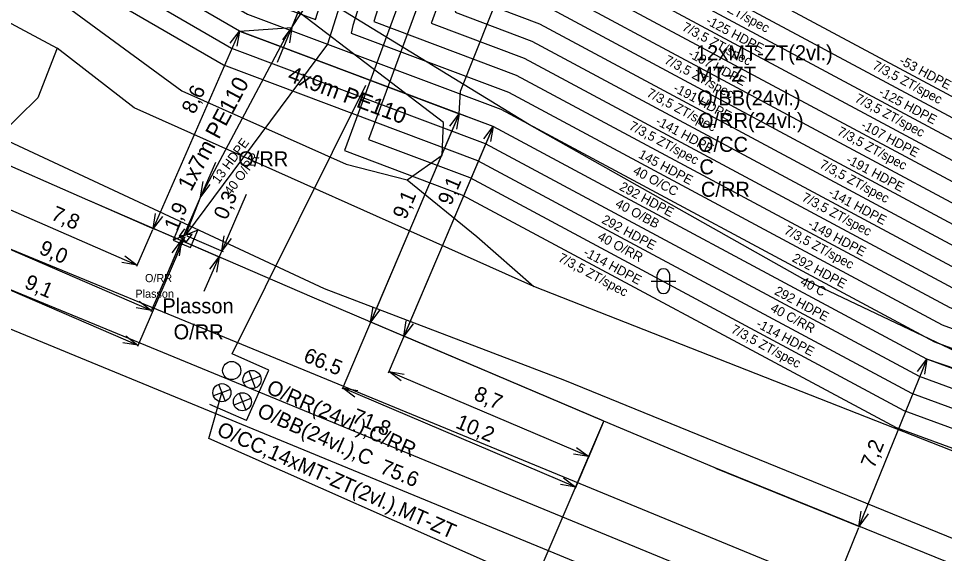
# Model space of a CAD drawing. Extents: x -836739 to -834468, y -1071001 to -1070126.
# Drawn here: x -836416.85 to -836379.75, y -1070403.2 to -1070381.77 of the extents above; entities that cross this region are included whole.
import ezdxf

# ---------------------------------------------------------------- set-up
doc = ezdxf.new("R2010")
doc.units = 0
for name, color, linetype in [('f001_pol_linie', 7, 'Continuous'), ('f001_pol_znacky', 7, 'Continuous'), ('f003_opt_sit_texty', 7, 'Continuous'), ('f003_opt_sit_znacky', 7, 'Continuous'), ('f006_osa_trasy', 7, 'Continuous'), ('f006_stp_koty', 7, 'Continuous'), ('f006_stp_linie', 7, 'Continuous'), ('f006_stp_texty', 7, 'Continuous'), ('f007_rezkynet_linie', 7, 'Continuous'), ('f007_rezkynet_texty', 7, 'Continuous'), ('f007_rezkynet_znacky', 7, 'Continuous'), ('f309_trub_konc_zar', 7, 'Continuous'), ('f309_trub_konc_zar_ann', 7, 'Continuous'), ('f309_trubicka', 7, 'Continuous'), ('f309_trubicka_ann', 7, 'Continuous'), ('f309_trubka', 7, 'Continuous'), ('f309_trubka_ann', 7, 'Continuous')]:
    doc.layers.add(name, color=color, linetype=linetype)

msp = doc.modelspace()

# ---------------------------------------------------------------- linework, layer by layer
at = {"layer": 'f001_pol_linie'}
for points in [[(-836356.62, -1070406.87), (-836370.19, -1070399.44), (-836385.43, -1070392.2), (-836396.38, -1070386.03), (-836404.41, -1070381.11), (-836409.87, -1070376.61), (-836425.28, -1070363.93), (-836449.03, -1070345.44), (-836455, -1070340), (-836462.64, -1070329.11), (-836464.81, -1070325.47), (-836465.74, -1070321.03), (-836464.89, -1070314.87), (-836461.62, -1070306.74), (-836456.41, -1070297.54), (-836450.95, -1070288.2), (-836447.03, -1070272.79), (-836441.38, -1070260.76)], [(-836496.52, -1070319.54), (-836488.05, -1070326.94), (-836479.74, -1070333.71), (-836473.51, -1070339.57), (-836464.27, -1070347.56), (-836456.25, -1070354.2), (-836445.54, -1070362.45), (-836432.86, -1070371.82), (-836421.65, -1070379.55), (-836415.3, -1070382.95)], [(-836490.91, -1070321.78), (-836479.74, -1070331.15), (-836472.55, -1070338.03), (-836463.6, -1070345.51), (-836457.27, -1070350.28), (-836449.01, -1070356.39), (-836440.87, -1070363.54), (-836429.17, -1070372.36), (-836419.16, -1070378.17), (-836410.31, -1070384.67), (-836403.72, -1070387.61), (-836401.28, -1070388.23), (-836398.49, -1070390.5), (-836396.2, -1070392.51)], [(-836401.28, -1070388.23), (-836399.88, -1070387.24), (-836399.82, -1070385.94), (-836405.57, -1070381.55), (-836407.8, -1070379.27), (-836409.87, -1070376.61)], [(-836415.3, -1070382.95), (-836416.08, -1070384.95), (-836417.67, -1070386.5), (-836418.22, -1070387.23)], [(-836363.94, -1070405.58), (-836375.83, -1070400.5), (-836396.2, -1070392.51), (-836412.22, -1070385.35), (-836415.3, -1070382.95)], [(-836417.67, -1070386.5), (-836404.61, -1070392.58), (-836394.98, -1070396.26), (-836377.21, -1070403.49), (-836366.86, -1070407.51), (-836361.89, -1070409.63)], [(-836393.4, -1070397.9), (-836405, -1070392.97), (-836414.08, -1070389.04), (-836418.22, -1070387.23), (-836418.59, -1070387.07)], [(-836407.72, -1070434.26), (-836404.42, -1070424.71), (-836401.63, -1070417.07), (-836396.94, -1070406.16), (-836393.4, -1070397.9)], [(-836369.71, -1070407.51), (-836374.95, -1070405.45), (-836388.98, -1070399.76), (-836393.4, -1070397.9)]]:
    msp.add_lwpolyline(points, dxfattribs=at)
at = {"layer": 'f001_pol_znacky'}
for p, q in [((-836391.26, -1070392.54), (-836391.26, -1070392.04)), ((-836390.76, -1070392.54), (-836390.76, -1070392.04)), ((-836391.51, -1070392.29), (-836390.51, -1070392.29))]:
    msp.add_line(p, q, dxfattribs=at)
for centre, start, end in [((-836391.01, -1070392.04), 0, 180), ((-836391.01, -1070392.54), 180, 360)]:
    msp.add_arc(centre, 0.25, start, end, dxfattribs=at)
at = {"layer": 'f003_opt_sit_znacky'}
msp.add_line((-836409.669, -1070390.25), (-836410.651, -1070390.65), dxfattribs=at)
msp.add_lwpolyline([(-836410.36, -1070389.959), (-836410.651, -1070390.65), (-836409.96, -1070390.941), (-836409.669, -1070390.25)], dxfattribs=at)
at = {"layer": 'f006_osa_trasy'}
for points in [[(-836399.2, -1070385.59), (-836399.14, -1070384.68), (-836393.13, -1070369.58), (-836388.15, -1070357.15), (-836383.97, -1070347.17), (-836386.96, -1070345.81), (-836384.62, -1070340.18)], [(-836408, -1070382.27), (-836428.93, -1070370.15), (-836435.11, -1070365.91)], [(-836405.9, -1070382.13), (-836404.46, -1070379.92)], [(-836408, -1070382.27), (-836405.9, -1070382.13)], [(-836405.9, -1070382.13), (-836406.05, -1070382.33), (-836406.35, -1070382.89)], [(-836406.35, -1070382.89), (-836408, -1070382.27)], [(-836406.35, -1070382.89), (-836409.56, -1070388.91), (-836410.16, -1070390.45)], [(-836399.2, -1070385.59), (-836406.35, -1070382.89)], [(-836374.26, -1070397.52), (-836380.46, -1070395.41), (-836397.84, -1070386.09), (-836399.2, -1070385.59)]]:
    msp.add_lwpolyline(points, dxfattribs=at)
at = {"layer": 'f006_stp_koty'}
for p, q in [((-836405.877, -1070382.075), (-836405.002, -1070379.95)), ((-836405.9, -1070382.13), (-836405.025, -1070380.006)), ((-836406.471, -1070383.517), (-836405.9, -1070382.13)), ((-836408, -1070382.27), (-836411.461, -1070390.185)), ((-836399.223, -1070385.645), (-836403.889, -1070396.623)), ((-836399.2, -1070385.59), (-836402.744, -1070393.929)), ((-836397.863, -1070386.145), (-836402.039, -1070395.971)), ((-836397.84, -1070386.09), (-836401.412, -1070394.495)), ((-836408.963, -1070387.534), (-836409.559, -1070388.91)), ((-836419.231, -1070388.537), (-836412.102, -1070391.652)), ((-836407.732, -1070388.82), (-836408.71, -1070391.078)), ((-836414.025, -1070389.064), (-836410.264, -1070390.691)), ((-836414.025, -1070389.064), (-836408.759, -1070391.343)), ((-836414.025, -1070389.064), (-836411.406, -1070390.209)), ((-836409.559, -1070388.91), (-836410.32, -1070390.668)), ((-836419.807, -1070389.885), (-836411.529, -1070393.464)), ((-836410.001, -1070389.93), (-836411.553, -1070393.519)), ((-836411.485, -1070390.24), (-836412.126, -1070391.707)), ((-836410.19, -1070390.52), (-836412.09, -1070394.913)), ((-836410.915, -1070392.044), (-836410.32, -1070390.668)), ((-836410.105, -1070390.474), (-836408.654, -1070391.102)), ((-836408.71, -1070391.078), (-836408.814, -1070391.319)), ((-836420.399, -1070391.255), (-836412.066, -1070394.858)), ((-836409.41, -1070392.696), (-836408.814, -1070391.319)), ((-836393.455, -1070397.877), (-836402.799, -1070393.905)), ((-836393.455, -1070397.877), (-836401.467, -1070394.471)), ((-836380.46, -1070395.41), (-836383.178, -1070402.113)), ((-836394.004, -1070399.32), (-836402.016, -1070395.915)), ((-836394.521, -1070400.539), (-836403.865, -1070396.567)), ((-836393.423, -1070397.955), (-836394.545, -1070400.594)), ((-836393.423, -1070397.955), (-836394.027, -1070399.376)), ((-836388.924, -1070399.783), (-836383.123, -1070402.135)), ((-836383.2, -1070402.169), (-836385.021, -1070406.712))]:
    msp.add_line(p, q, dxfattribs=at)
for points in [[(-836406.267, -1070382.628), (-836405.9, -1070382.13), (-836405.99, -1070382.742)], [(-836408.378, -1070382.76), (-836408, -1070382.27), (-836408.103, -1070382.88)], [(-836435.495, -1070383.458), (-836373.991, -1070408.776)], [(-836436.07, -1070384.855), (-836369.694, -1070412.179)], [(-836399.573, -1070386.084), (-836399.2, -1070385.59), (-836399.297, -1070386.201)], [(-836436.625, -1070386.205), (-836366.711, -1070414.986)], [(-836398.213, -1070386.584), (-836397.84, -1070386.09), (-836397.937, -1070386.701)], [(-836409.183, -1070388.419), (-836409.559, -1070388.91), (-836409.458, -1070388.3)], [(-836411.083, -1070389.696), (-836411.461, -1070390.185), (-836411.358, -1070389.575)], [(-836410.696, -1070391.159), (-836410.32, -1070390.668), (-836410.42, -1070391.278)], [(-836408.334, -1070390.587), (-836408.71, -1070391.078), (-836408.609, -1070390.468)], [(-836412.592, -1070391.274), (-836412.102, -1070391.652), (-836412.712, -1070391.549)], [(-836409.19, -1070391.81), (-836408.814, -1070391.319), (-836408.915, -1070391.929)], [(-836412.02, -1070393.088), (-836411.529, -1070393.464), (-836412.139, -1070393.364)], [(-836402.371, -1070393.435), (-836402.744, -1070393.929), (-836402.647, -1070393.318)], [(-836401.039, -1070394.001), (-836401.412, -1070394.495), (-836401.315, -1070393.884)], [(-836412.557, -1070394.483), (-836412.066, -1070394.858), (-836412.676, -1070394.758)], [(-836380.825, -1070395.91), (-836380.46, -1070395.41), (-836380.546, -1070396.022)], [(-836401.522, -1070396.288), (-836402.016, -1070395.915), (-836401.405, -1070396.012)], [(-836403.372, -1070396.94), (-836403.865, -1070396.567), (-836403.255, -1070396.664)], [(-836394.497, -1070398.948), (-836394.004, -1070399.32), (-836394.615, -1070399.224)], [(-836395.015, -1070400.166), (-836394.521, -1070400.539), (-836395.132, -1070400.442)], [(-836382.814, -1070401.613), (-836383.178, -1070402.113), (-836383.092, -1070401.5)]]:
    msp.add_lwpolyline(points, dxfattribs=at)
at = {"layer": 'f006_stp_linie'}
for points in [[(-836406.05, -1070382.33), (-836406.35, -1070382.89), (-836409.56, -1070388.91)], [(-836408, -1070382.27), (-836406.35, -1070382.89), (-836399.2, -1070385.59)]]:
    msp.add_lwpolyline(points, dxfattribs=at)
at = {"layer": 'f007_rezkynet_linie'}
for points in [[(-836408.289, -1070395.202), (-836402.942, -1070384.445)], [(-836397.3, -1070403.879), (-836409.223, -1070398.599), (-836408.703, -1070396.758)]]:
    msp.add_lwpolyline(points, dxfattribs=at)
at = {"layer": 'f007_rezkynet_znacky'}
for p, q in [((-836406.826, -1070395.85), (-836408.289, -1070395.202)), ((-836407.719, -1070397.868), (-836406.826, -1070395.85)), ((-836407.628, -1070395.892), (-836407.366, -1070396.569)), ((-836407.158, -1070396.1), (-836407.836, -1070396.361)), ((-836408.364, -1070396.627), (-836409.042, -1070396.888)), ((-836408.834, -1070396.419), (-836408.572, -1070397.096)), ((-836407.542, -1070396.991), (-836408.219, -1070397.252)), ((-836408.012, -1070396.783), (-836407.749, -1070397.46)), ((-836409.197, -1070397.214), (-836407.734, -1070397.861))]:
    msp.add_line(p, q, dxfattribs=at)
for centre in [(-836408.311, -1070395.87), (-836407.497, -1070396.231), (-836408.703, -1070396.758), (-836407.881, -1070397.122)]:
    msp.add_circle(centre, 0.363, dxfattribs=at)
at = {"layer": 'f309_trub_konc_zar'}
msp.add_line((-836409.898, -1070390.411), (-836410.422, -1070390.489), dxfattribs=at)
msp.add_lwpolyline([(-836410.199, -1070390.188), (-836410.422, -1070390.489), (-836410.121, -1070390.712), (-836409.898, -1070390.411)], dxfattribs=at)
at = {"layer": 'f309_trubicka'}
for points in [[(-836400.273, -1070369.489), (-836391.917, -1070372.915), (-836392.98, -1070376.276), (-836393.807, -1070378.894), (-836377.072, -1070387.864), (-836347.119, -1070398.841), (-836346.84, -1070398.955), (-836333.059, -1070367.084), (-836330.504, -1070368.102), (-836328.325, -1070362.967), (-836330.838, -1070361.855), (-836330.397, -1070360.859)], [(-836400.273, -1070369.489), (-836392.632, -1070372.689), (-836393.695, -1070376.05), (-836394.709, -1070379.261), (-836377.38, -1070388.55), (-836347.39, -1070399.54), (-836346.443, -1070399.927), (-836332.66, -1070368.05), (-836330.1, -1070369.07), (-836327.64, -1070363.27), (-836325.462, -1070364.234), (-836325.022, -1070363.239)], [(-836400.273, -1070369.489), (-836398.353, -1070370.882), (-836399.415, -1070374.242), (-836401.469, -1070380.743), (-836403.793, -1070387.056), (-836399.084, -1070388.826), (-836381.692, -1070398.154), (-836351.184, -1070409.34), (-836324.48, -1070420.23), (-836327.076, -1070426.64), (-836328.57, -1070426.6)], [(-836400.273, -1070369.489), (-836397.638, -1070371.108), (-836398.7, -1070374.468), (-836400.759, -1070380.986), (-836402.832, -1070386.616), (-836398.773, -1070388.142), (-836381.384, -1070397.468), (-836350.913, -1070408.64), (-836323.504, -1070419.818), (-836326.34, -1070426.82), (-836326.51, -1070428.61)], [(-836400.273, -1070369.489), (-836399.069, -1070370.656), (-836400.13, -1070374.016), (-836402.617, -1070381.89), (-836396.907, -1070384.038), (-836379.536, -1070393.352), (-836349.287, -1070404.44), (-836286.052, -1070430.233), (-836290.016, -1070440.999), (-836290.881, -1070443.349)], [(-836400.273, -1070369.489), (-836396.208, -1070371.559), (-836397.27, -1070374.92), (-836399.339, -1070381.472), (-836399.355, -1070381.515), (-836396.285, -1070382.67), (-836378.92, -1070391.98), (-836348.745, -1070403.04), (-836289.137, -1070427.354), (-836286.713, -1070421.411), (-836283.062, -1070422.901)], [(-836400.273, -1070369.489), (-836394.777, -1070372.011), (-836395.84, -1070375.372), (-836397.495, -1070380.612), (-836395.663, -1070381.302), (-836378.304, -1070390.608), (-836348.203, -1070401.64), (-836289.959, -1070425.398), (-836287.821, -1070420.156), (-836276.772, -1070391.607), (-836279.008, -1070390.66), (-836276.322, -1070384.183), (-836278.31, -1070383.359), (-836277.858, -1070382.269)], [(-836400.273, -1070369.489), (-836395.493, -1070371.785), (-836396.555, -1070375.146), (-836398.424, -1070381.064), (-836395.974, -1070381.986), (-836378.612, -1070391.294), (-836348.474, -1070402.34), (-836289.548, -1070426.376), (-836287.124, -1070420.433), (-836275.81, -1070391.2), (-836278.03, -1070390.26), (-836275.63, -1070384.47), (-836273.812, -1070385.224), (-836273.367, -1070384.131)], [(-836400.273, -1070369.489), (-836394.062, -1070372.237), (-836395.125, -1070375.598), (-836396.566, -1070380.161), (-836395.352, -1070380.618), (-836377.996, -1070389.922), (-836347.932, -1070400.94), (-836316.686, -1070413.686), (-836314.602, -1070408.659), (-836312.289, -1070409.618)], [(-836400.273, -1070369.489), (-836393.347, -1070372.463), (-836394.41, -1070375.824), (-836395.637, -1070379.709), (-836395.041, -1070379.934), (-836377.688, -1070389.236), (-836347.661, -1070400.24), (-836317.093, -1070412.71), (-836315.295, -1070408.372), (-836317.789, -1070407.338)], [(-836400.273, -1070369.489), (-836391.202, -1070373.141), (-836392.265, -1070376.502), (-836392.904, -1070378.527), (-836376.764, -1070387.178), (-836369.286, -1070389.919), (-836367.531, -1070385.13), (-836366.11, -1070385.651)], [(-836400.273, -1070369.489), (-836390.486, -1070373.366), (-836391.55, -1070376.728), (-836392.002, -1070378.16), (-836376.456, -1070386.492), (-836369.732, -1070388.957), (-836368.235, -1070384.872), (-836369.508, -1070384.405)], [(-836397.141, -1070372.024), (-836397.985, -1070374.694), (-836400.049, -1070381.229), (-836400.305, -1070381.924), (-836400.312, -1070381.956), (-836396.596, -1070383.354), (-836379.228, -1070392.666), (-836349.016, -1070403.74), (-836288.726, -1070428.332), (-836286.302, -1070422.389), (-836283.345, -1070423.595)]]:
    msp.add_lwpolyline(points, dxfattribs=at)
at = {"layer": 'f309_trubka'}
for points in [[(-836257.543, -1070422.322), (-836258.258, -1070422.096), (-836259.283, -1070421.772), (-836260.99, -1070422.47), (-836266.6, -1070439.21), (-836271.52, -1070438.59), (-836350.1, -1070406.54), (-836380.46, -1070395.41), (-836397.84, -1070386.09), (-836408, -1070382.27), (-836428.93, -1070370.15), (-836446.35, -1070358.45), (-836497.8, -1070313.84), (-836500.259, -1070310.812)], [(-836500.901, -1070311.21), (-836500.428, -1070311.792), (-836498.049, -1070311.154), (-836496.718, -1070312.792), (-836445.438, -1070357.256), (-836428.136, -1070368.876), (-836407.356, -1070380.91), (-836404.953, -1070381.813), (-836402.275, -1070373.338)], [(-836499.139, -1070311.001), (-836497.259, -1070313.316), (-836445.894, -1070357.853), (-836428.533, -1070369.513), (-836407.678, -1070381.59), (-836397.529, -1070385.406), (-836380.152, -1070394.724), (-836349.829, -1070405.84), (-836271.328, -1070437.858), (-836267.116, -1070438.389), (-836261.592, -1070421.906), (-836259.316, -1070420.975), (-836258.032, -1070421.38), (-836257.317, -1070421.606)], [(-836501.069, -1070312.194), (-836498.882, -1070314.888), (-836447.262, -1070359.644), (-836429.724, -1070371.424), (-836408.644, -1070383.63), (-836398.462, -1070387.458), (-836381.076, -1070396.782), (-836350.642, -1070407.94), (-836271.904, -1070440.054), (-836265.568, -1070440.852), (-836259.786, -1070423.598), (-836259.218, -1070423.366), (-836257.995, -1070423.753)], [(-836499.902, -1070312.441), (-836498.341, -1070314.364), (-836446.806, -1070359.047), (-836429.327, -1070370.787), (-836408.322, -1070382.95), (-836398.151, -1070386.774), (-836380.768, -1070396.096), (-836350.371, -1070407.24), (-836271.712, -1070439.322), (-836266.084, -1070440.031), (-836260.388, -1070423.034), (-836259.25, -1070422.569), (-836257.769, -1070423.038)], [(-836401.56, -1070373.564), (-836404.476, -1070382.793), (-836410.16, -1070390.45)], [(-836400.845, -1070373.79), (-836403.452, -1070382.042), (-836403.525, -1070382.35), (-836397.218, -1070384.722), (-836379.844, -1070394.038), (-836349.558, -1070405.14), (-836287.006, -1070430.654), (-836290.72, -1070440.74)]]:
    msp.add_lwpolyline(points, dxfattribs=at)

# ---------------------------------------------------------------- texts
at = {"layer": 'f003_opt_sit_texty'}
for s, p in [('12xMT-ZT(2vl.)', (-836389.71, -1070383.44)), ('MT-ZT', (-836389.71, -1070384.3)), ('O/BB(24vl.)', (-836389.66, -1070385.25)), ('O/RR(24vl.)', (-836389.63, -1070386.15)), ('O/CC', (-836389.63, -1070387.11)), ('O/RR', (-836408.05, -1070387.69)), ('C', (-836389.57, -1070388.01)), ('C/RR', (-836389.51, -1070388.91)), ('Plasson', (-836411.09, -1070393.58)), ('O/RR', (-836410.64, -1070394.62))]:
    msp.add_text(s, height=0.6, dxfattribs=at).set_placement(p)
at = {"layer": 'f006_stp_koty'}
for s, rotation, p in [('8,6', 66.3851, (-836409.796, -1070385.63)), ('9,1', 66.9745, (-836399.528, -1070389.295)), ('0,3', 66.5961, (-836408.514, -1070389.871)), ('9,1', 66.9745, (-836401.337, -1070389.851)), ('1,9', 66.5961, (-836410.497, -1070390.323)), ('7,8', 336.3972, (-836415.591, -1070389.8)), ('9,0', 336.6148, (-836416.069, -1070391.174)), ('9,1', 336.6148, (-836416.657, -1070392.546)), ('66.5', 337.63, (-836405.477, -1070395.489)), ('8,7', 336.9745, (-836398.65, -1070397.02)), ('71.8', 337.63, (-836403.535, -1070397.922)), ('10,2', 336.9745, (-836399.379, -1070398.148)), ('7,2', 67.9245, (-836382.574, -1070399.825)), ('75.6', 337.63, (-836402.415, -1070399.962))]:
    msp.add_text(s, height=0.6, rotation=rotation, dxfattribs=at).set_placement(p)
at = {"layer": 'f006_stp_texty'}
for s, rotation, p in [('4x9m PE110', 339.3299, (-836406.114, -1070384.257)), ('1x7m PE110', 61.923, (-836409.94, -1070388.73))]:
    msp.add_text(s, height=0.65, rotation=rotation, dxfattribs=at).set_placement(p)
at = {"layer": 'f007_rezkynet_texty'}
for s, p in [('O/RR(24vl.),C/RR', (-836406.962, -1070396.754)), ('O/BB(24vl.),C', (-836407.335, -1070397.69)), ('O/CC,14xMT-ZT(2vl.),MT-ZT', (-836408.95, -1070398.44))]:
    msp.add_text(s, height=0.6, rotation=336.1153, dxfattribs=at).set_placement(p)
at = {"layer": 'f309_trub_konc_zar_ann'}
for s, p in [('O/RR', (-836411.786, -1070392.33)), ('Plasson', (-836412.171, -1070392.955))]:
    msp.add_text(s, height=0.325, dxfattribs=at).set_placement(p)
at = {"layer": 'f309_trubicka_ann'}
for s, rotation, p in [('7/3,5 ZT/spec', 331.8088, (-836389.589, -1070380.899)), ('-125 HDPE', 331.807, (-836389.346, -1070381.966)), ('7/3,5 ZT/spec', 331.807, (-836390.298, -1070382.221)), ('7/3,5 ZT/spec', 331.8057, (-836391.007, -1070383.543)), ('-107 HDPE', 331.8057, (-836390.054, -1070383.288)), ('7/3,5 ZT/spec', 331.8106, (-836382.666, -1070383.76)), ('-53 HDPE', 331.8106, (-836381.596, -1070383.567)), ('7/3,5 ZT/spec', 331.8036, (-836391.716, -1070384.865)), ('-191 HDPE', 331.8036, (-836390.651, -1070384.669)), ('7/3,5 ZT/spec', 331.8086, (-836383.375, -1070385.081)), ('-125 HDPE', 331.8086, (-836382.422, -1070384.826)), ('7/3,5 ZT/spec', 331.8016, (-836392.424, -1070386.186)), ('-141 HDPE', 331.8016, (-836391.36, -1070385.991)), ('7/3,5 ZT/spec', 331.8067, (-836384.083, -1070386.403)), ('-107 HDPE', 331.8067, (-836383.131, -1070386.148)), ('-191 HDPE', 331.8047, (-836383.728, -1070387.53)), ('7/3,5 ZT/spec', 331.8047, (-836384.792, -1070387.725)), ('7/3,5 ZT/spec', 331.8026, (-836385.501, -1070389.047)), ('-141 HDPE', 331.8026, (-836384.437, -1070388.852)), ('-149 HDPE', 331.8006, (-836385.258, -1070390.114)), ('7/3,5 ZT/spec', 331.8006, (-836386.21, -1070390.369)), ('-114 HDPE', 331.7936, (-836394.252, -1070391.248)), ('7/3,5 ZT/spec', 331.7936, (-836395.26, -1070391.473)), ('7/3,5 ZT/spec', 331.7946, (-836388.337, -1070394.335)), ('-114 HDPE', 331.7946, (-836387.328, -1070394.11))]:
    msp.add_text(s, height=0.375, rotation=rotation, dxfattribs=at).set_placement(p)
at = {"layer": 'f309_trubka_ann'}
for s, rotation, p in [('13 HDPE', 53.4125, (-836408.837, -1070388.416)), ('40 O/RR', 53.4125, (-836408.344, -1070388.885)), ('145 HDPE', 331.7996, (-836392.045, -1070387.325)), ('40 O/CC', 331.7996, (-836392.264, -1070387.974)), ('292 HDPE', 331.7976, (-836392.81, -1070388.617)), ('40 O/BB', 331.7976, (-836392.973, -1070389.296)), ('292 HDPE', 331.7956, (-836393.519, -1070389.939)), ('40 O/RR', 331.7956, (-836393.682, -1070390.617)), ('292 HDPE', 331.7986, (-836385.887, -1070391.479)), ('40 C', 331.7986, (-836385.562, -1070392.419)), ('292 HDPE', 331.7966, (-836386.596, -1070392.8)), ('40 C/RR', 331.7966, (-836386.759, -1070393.479))]:
    msp.add_text(s, height=0.375, rotation=rotation, dxfattribs=at).set_placement(p)

doc.saveas('drawing.dxf')
